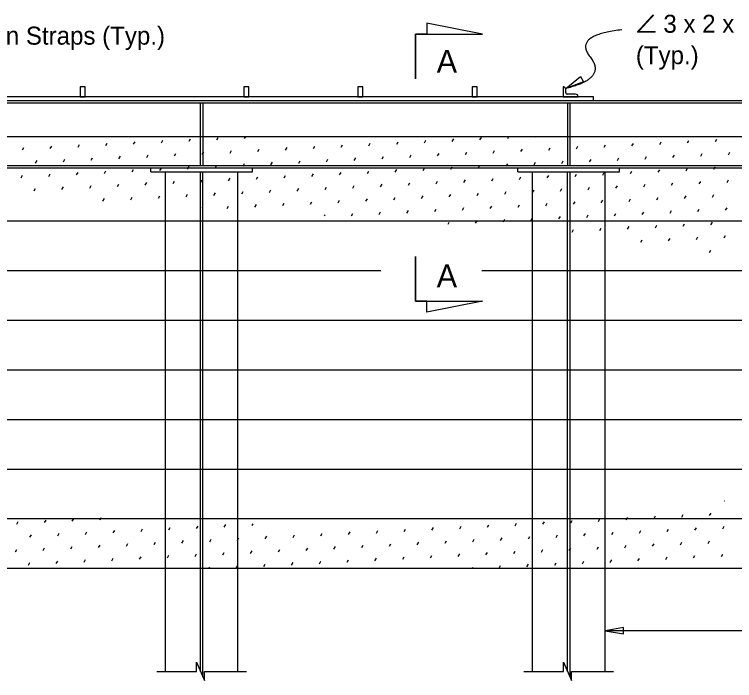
# Model space of a CAD drawing. Extents: x 10624 to 10731, y 76457 to 76509.
# Drawn here: x 10653.36 to 10665.46, y 76483.76 to 76494.95 of the extents above; entities that cross this region are included whole.
import ezdxf

# ---------------------------------------------------------------- set-up
doc = ezdxf.new("R2010")
doc.units = 0
for name, color, linetype in [('Dimension', 7, 'Continuous'), ('GroundLines', 7, 'Continuous'), ('SteelMisc', 7, 'Continuous'), ('SteelMisc_h', 7, 'Continuous'), ('Symbols', 7, 'Continuous'), ('TextStructures', 7, 'Continuous'), ('Wood', 7, 'Continuous'), ('Wood_h', 7, 'Continuous')]:
    doc.layers.add(name, color=color, linetype=linetype)

msp = doc.modelspace()

# ---------------------------------------------------------------- linework, layer by layer
at = {"layer": 'Dimension'}
for p, q in [((10655.365, 76492.769), (10655.389, 76492.811)), ((10655.831, 76492.793), (10655.855, 76492.835)), ((10656.298, 76492.818), (10656.322, 76492.86)), ((10656.764, 76492.842), (10656.788, 76492.884)), ((10657.23, 76492.866), (10657.248, 76492.897)), ((10657.697, 76492.891), (10657.701, 76492.897)), ((10659.784, 76492.767), (10659.808, 76492.809)), ((10660.25, 76492.792), (10660.274, 76492.834)), ((10660.717, 76492.816), (10660.741, 76492.858)), ((10661.183, 76492.84), (10661.207, 76492.882)), ((10661.649, 76492.865), (10661.668, 76492.897)), ((10662.116, 76492.889), (10662.121, 76492.897)), ((10664.203, 76492.765), (10664.227, 76492.807)), ((10664.669, 76492.79), (10664.693, 76492.832)), ((10665.136, 76492.814), (10665.16, 76492.856)), ((10653.499, 76492.672), (10653.523, 76492.714)), ((10653.965, 76492.696), (10653.99, 76492.738)), ((10654.432, 76492.72), (10654.456, 76492.762)), ((10654.898, 76492.745), (10654.922, 76492.787)), ((10657.451, 76492.645), (10657.476, 76492.687)), ((10657.918, 76492.67), (10657.942, 76492.712)), ((10658.384, 76492.694), (10658.409, 76492.736)), ((10658.851, 76492.718), (10658.875, 76492.76)), ((10659.317, 76492.743), (10659.341, 76492.785)), ((10661.87, 76492.644), (10661.895, 76492.686)), ((10662.337, 76492.668), (10662.361, 76492.71)), ((10662.803, 76492.692), (10662.828, 76492.734)), ((10663.27, 76492.717), (10663.294, 76492.759)), ((10663.736, 76492.741), (10663.76, 76492.783)), ((10655.119, 76492.524), (10655.144, 76492.566)), ((10655.586, 76492.548), (10655.61, 76492.59)), ((10656.052, 76492.572), (10656.076, 76492.614)), ((10656.519, 76492.597), (10656.543, 76492.639)), ((10656.985, 76492.621), (10657.009, 76492.663)), ((10659.538, 76492.522), (10659.563, 76492.564)), ((10660.005, 76492.546), (10660.029, 76492.588)), ((10660.471, 76492.571), (10660.495, 76492.613)), ((10660.938, 76492.595), (10660.962, 76492.637)), ((10661.404, 76492.619), (10661.428, 76492.661)), ((10664.424, 76492.544), (10664.448, 76492.586)), ((10664.89, 76492.569), (10664.914, 76492.611)), ((10665.357, 76492.593), (10665.381, 76492.635)), ((10653.72, 76492.451), (10653.744, 76492.493)), ((10654.186, 76492.475), (10654.211, 76492.517)), ((10654.653, 76492.499), (10654.677, 76492.541)), ((10657.206, 76492.4), (10657.23, 76492.442)), ((10657.672, 76492.424), (10657.697, 76492.466)), ((10658.139, 76492.449), (10658.163, 76492.491)), ((10658.605, 76492.473), (10658.63, 76492.515)), ((10659.072, 76492.497), (10659.096, 76492.539)), ((10662.091, 76492.423), (10662.116, 76492.465)), ((10662.558, 76492.447), (10662.582, 76492.489)), ((10663.024, 76492.471), (10663.049, 76492.513)), ((10663.491, 76492.496), (10663.515, 76492.538)), ((10663.957, 76492.52), (10663.982, 76492.562)), ((10655.34, 76492.303), (10655.365, 76492.345)), ((10655.807, 76492.327), (10655.831, 76492.369)), ((10656.273, 76492.351), (10656.297, 76492.393)), ((10656.74, 76492.376), (10656.764, 76492.418)), ((10659.759, 76492.301), (10659.784, 76492.343)), ((10660.226, 76492.325), (10660.25, 76492.367)), ((10660.692, 76492.349), (10660.716, 76492.391)), ((10661.159, 76492.374), (10661.183, 76492.416)), ((10661.625, 76492.398), (10661.649, 76492.44)), ((10664.178, 76492.299), (10664.203, 76492.341)), ((10664.645, 76492.323), (10664.669, 76492.365)), ((10665.111, 76492.348), (10665.135, 76492.39)), ((10653.475, 76492.205), (10653.499, 76492.247)), ((10653.941, 76492.229), (10653.965, 76492.271)), ((10654.407, 76492.254), (10654.432, 76492.296)), ((10654.874, 76492.278), (10654.898, 76492.32)), ((10657.427, 76492.179), (10657.451, 76492.221)), ((10657.894, 76492.203), (10657.918, 76492.245)), ((10658.36, 76492.228), (10658.384, 76492.27)), ((10658.826, 76492.252), (10658.851, 76492.294)), ((10659.293, 76492.276), (10659.317, 76492.318)), ((10661.846, 76492.177), (10661.87, 76492.219)), ((10662.313, 76492.202), (10662.337, 76492.244)), ((10662.779, 76492.226), (10662.803, 76492.268)), ((10663.245, 76492.25), (10663.27, 76492.292)), ((10663.712, 76492.275), (10663.736, 76492.317)), ((10655.095, 76492.057), (10655.119, 76492.099)), ((10655.561, 76492.082), (10655.586, 76492.124)), ((10656.028, 76492.106), (10656.052, 76492.148)), ((10656.494, 76492.13), (10656.518, 76492.172)), ((10656.961, 76492.155), (10656.985, 76492.197)), ((10659.514, 76492.055), (10659.538, 76492.097)), ((10659.98, 76492.08), (10660.005, 76492.122)), ((10660.447, 76492.104), (10660.471, 76492.146)), ((10660.913, 76492.128), (10660.937, 76492.17)), ((10661.38, 76492.153), (10661.404, 76492.195)), ((10663.933, 76492.054), (10663.957, 76492.096)), ((10664.399, 76492.078), (10664.424, 76492.12)), ((10664.866, 76492.102), (10664.89, 76492.144)), ((10665.332, 76492.127), (10665.356, 76492.169)), ((10653.696, 76491.984), (10653.72, 76492.026)), ((10654.162, 76492.008), (10654.186, 76492.05)), ((10654.628, 76492.033), (10654.653, 76492.075)), ((10657.182, 76491.934), (10657.206, 76491.976)), ((10657.648, 76491.958), (10657.672, 76492)), ((10658.115, 76491.982), (10658.139, 76492.024)), ((10658.581, 76492.007), (10658.605, 76492.049)), ((10659.047, 76492.031), (10659.072, 76492.073)), ((10661.601, 76491.932), (10661.625, 76491.974)), ((10662.067, 76491.956), (10662.091, 76491.998)), ((10662.534, 76491.98), (10662.558, 76492.022)), ((10663, 76492.005), (10663.024, 76492.047)), ((10663.466, 76492.029), (10663.491, 76492.071)), ((10654.849, 76491.812), (10654.874, 76491.854)), ((10655.316, 76491.836), (10655.34, 76491.878)), ((10655.782, 76491.86), (10655.807, 76491.902)), ((10656.249, 76491.885), (10656.273, 76491.927)), ((10656.715, 76491.909), (10656.74, 76491.951)), ((10659.268, 76491.81), (10659.293, 76491.852)), ((10659.735, 76491.834), (10659.759, 76491.876)), ((10660.201, 76491.859), (10660.226, 76491.901)), ((10660.668, 76491.883), (10660.692, 76491.925)), ((10661.134, 76491.907), (10661.159, 76491.949)), ((10663.687, 76491.808), (10663.712, 76491.85)), ((10664.154, 76491.833), (10664.178, 76491.874)), ((10664.62, 76491.857), (10664.645, 76491.899)), ((10665.087, 76491.881), (10665.111, 76491.923)), ((10656.936, 76491.688), (10656.961, 76491.73)), ((10657.403, 76491.713), (10657.427, 76491.755)), ((10657.869, 76491.737), (10657.893, 76491.779)), ((10658.336, 76491.761), (10658.36, 76491.803)), ((10658.802, 76491.786), (10658.826, 76491.828)), ((10661.355, 76491.686), (10661.38, 76491.728)), ((10661.822, 76491.711), (10661.846, 76491.753)), ((10662.288, 76491.735), (10662.312, 76491.777)), ((10662.755, 76491.759), (10662.779, 76491.801)), ((10663.221, 76491.784), (10663.245, 76491.826)), ((10656.492, 76491.702), (10656.494, 76491.706)), ((10659.023, 76491.565), (10659.047, 76491.607)), ((10659.49, 76491.589), (10659.514, 76491.631)), ((10659.956, 76491.613), (10659.98, 76491.655)), ((10660.422, 76491.638), (10660.447, 76491.68)), ((10660.889, 76491.662), (10660.913, 76491.704)), ((10663.442, 76491.563), (10663.466, 76491.605)), ((10663.909, 76491.587), (10663.933, 76491.629)), ((10664.375, 76491.611), (10664.399, 76491.653)), ((10664.841, 76491.636), (10664.866, 76491.678)), ((10665.308, 76491.66), (10665.332, 76491.702)), ((10658.571, 76491.564), (10658.581, 76491.582)), ((10661.11, 76491.441), (10661.134, 76491.483)), ((10661.576, 76491.465), (10661.601, 76491.507)), ((10662.043, 76491.49), (10662.067, 76491.532)), ((10662.509, 76491.514), (10662.533, 76491.556)), ((10662.976, 76491.538), (10663, 76491.58)), ((10660.649, 76491.427), (10660.668, 76491.459)), ((10663.197, 76491.317), (10663.221, 76491.359)), ((10663.663, 76491.342), (10663.687, 76491.384)), ((10664.13, 76491.366), (10664.154, 76491.408)), ((10664.596, 76491.39), (10664.62, 76491.432)), ((10665.062, 76491.415), (10665.087, 76491.457)), ((10662.73, 76491.293), (10662.755, 76491.335)), ((10665.283, 76491.194), (10665.308, 76491.236)), ((10663.884, 76491.121), (10663.908, 76491.163)), ((10664.351, 76491.145), (10664.375, 76491.187)), ((10664.817, 76491.169), (10664.841, 76491.211)), ((10665.038, 76490.948), (10665.062, 76490.99)), ((10665.285, 76486.775), (10665.288, 76486.78)), ((10664.107, 76486.481), (10664.131, 76486.523)), ((10664.573, 76486.505), (10664.598, 76486.547)), ((10665.04, 76486.529), (10665.064, 76486.571)), ((10653.403, 76486.387), (10653.428, 76486.429)), ((10653.87, 76486.411), (10653.894, 76486.453)), ((10654.336, 76486.436), (10654.36, 76486.478)), ((10654.803, 76486.46), (10654.823, 76486.496)), ((10661.775, 76486.359), (10661.799, 76486.401)), ((10662.241, 76486.383), (10662.266, 76486.425)), ((10662.708, 76486.408), (10662.732, 76486.45)), ((10663.174, 76486.432), (10663.198, 76486.474)), ((10663.641, 76486.456), (10663.665, 76486.498)), ((10655.024, 76486.239), (10655.048, 76486.281)), ((10655.49, 76486.263), (10655.514, 76486.305)), ((10655.956, 76486.288), (10655.981, 76486.33)), ((10656.423, 76486.312), (10656.447, 76486.354)), ((10656.889, 76486.336), (10656.914, 76486.378)), ((10657.356, 76486.361), (10657.373, 76486.391)), ((10659.443, 76486.237), (10659.467, 76486.279)), ((10659.909, 76486.261), (10659.933, 76486.303)), ((10660.375, 76486.286), (10660.4, 76486.328)), ((10660.842, 76486.31), (10660.866, 76486.352)), ((10661.308, 76486.334), (10661.333, 76486.376)), ((10663.862, 76486.235), (10663.886, 76486.277)), ((10664.328, 76486.26), (10664.352, 76486.302)), ((10664.794, 76486.284), (10664.819, 76486.326)), ((10665.261, 76486.308), (10665.285, 76486.35)), ((10653.624, 76486.166), (10653.649, 76486.208)), ((10654.091, 76486.19), (10654.115, 76486.232)), ((10654.557, 76486.214), (10654.581, 76486.256)), ((10657.11, 76486.115), (10657.135, 76486.157)), ((10657.577, 76486.14), (10657.601, 76486.182)), ((10658.043, 76486.164), (10658.068, 76486.206)), ((10658.51, 76486.188), (10658.534, 76486.23)), ((10658.976, 76486.213), (10659, 76486.255)), ((10661.529, 76486.113), (10661.554, 76486.155)), ((10661.996, 76486.138), (10662.02, 76486.18)), ((10662.462, 76486.162), (10662.487, 76486.204)), ((10662.929, 76486.187), (10662.953, 76486.229)), ((10663.395, 76486.211), (10663.419, 76486.253)), ((10654.778, 76485.993), (10654.803, 76486.035)), ((10655.245, 76486.018), (10655.269, 76486.06)), ((10655.711, 76486.042), (10655.735, 76486.084)), ((10656.178, 76486.067), (10656.202, 76486.109)), ((10656.644, 76486.091), (10656.668, 76486.133)), ((10659.197, 76485.992), (10659.222, 76486.034)), ((10659.664, 76486.016), (10659.688, 76486.058)), ((10660.13, 76486.04), (10660.154, 76486.082)), ((10660.597, 76486.065), (10660.621, 76486.107)), ((10661.063, 76486.089), (10661.087, 76486.131)), ((10663.616, 76485.99), (10663.641, 76486.032)), ((10664.083, 76486.014), (10664.107, 76486.056)), ((10664.549, 76486.039), (10664.573, 76486.081)), ((10665.016, 76486.063), (10665.04, 76486.105)), ((10653.379, 76485.92), (10653.403, 76485.962)), ((10653.845, 76485.945), (10653.87, 76485.987)), ((10654.312, 76485.969), (10654.336, 76486.011)), ((10656.865, 76485.87), (10656.889, 76485.912)), ((10657.331, 76485.894), (10657.356, 76485.936)), ((10657.798, 76485.919), (10657.822, 76485.961)), ((10658.264, 76485.943), (10658.289, 76485.985)), ((10658.731, 76485.967), (10658.755, 76486.009)), ((10661.284, 76485.868), (10661.308, 76485.91)), ((10661.75, 76485.892), (10661.775, 76485.934)), ((10662.217, 76485.917), (10662.241, 76485.959)), ((10662.683, 76485.941), (10662.708, 76485.983)), ((10663.15, 76485.965), (10663.174, 76486.007)), ((10654.533, 76485.748), (10654.557, 76485.79)), ((10654.999, 76485.772), (10655.024, 76485.814)), ((10655.466, 76485.797), (10655.49, 76485.839)), ((10655.932, 76485.821), (10655.956, 76485.863)), ((10656.399, 76485.845), (10656.423, 76485.887)), ((10659.418, 76485.771), (10659.443, 76485.813)), ((10659.885, 76485.795), (10659.909, 76485.837)), ((10660.351, 76485.819), (10660.375, 76485.861)), ((10660.818, 76485.844), (10660.842, 76485.886)), ((10663.837, 76485.769), (10663.862, 76485.811)), ((10664.304, 76485.793), (10664.328, 76485.835)), ((10664.77, 76485.818), (10664.794, 76485.859)), ((10665.237, 76485.842), (10665.261, 76485.884)), ((10653.6, 76485.699), (10653.624, 76485.741)), ((10654.066, 76485.724), (10654.091, 76485.766)), ((10657.086, 76485.649), (10657.11, 76485.691)), ((10657.552, 76485.673), (10657.577, 76485.715)), ((10658.019, 76485.698), (10658.043, 76485.74)), ((10658.485, 76485.722), (10658.51, 76485.764)), ((10658.952, 76485.746), (10658.976, 76485.788)), ((10661.505, 76485.647), (10661.529, 76485.689)), ((10661.971, 76485.671), (10661.996, 76485.713)), ((10662.438, 76485.696), (10662.462, 76485.738)), ((10662.904, 76485.72), (10662.929, 76485.762)), ((10663.371, 76485.744), (10663.395, 76485.786)), ((10656.177, 76485.641), (10656.177, 76485.642)), ((10656.629, 76485.641), (10656.644, 76485.666)), ((10661.049, 76485.641), (10661.063, 76485.665)), ((10670.147, 76484.596), (10663.283, 76484.596))]:
    msp.add_line(p, q, dxfattribs=at)
for points in [[(10662.624, 76493.705), (10662.869, 76493.906), (10662.921, 76493.815)], [(10663.283, 76484.596), (10663.595, 76484.543), (10663.595, 76484.649)]]:
    msp.add_lwpolyline(points, close=True, dxfattribs=at)
msp.add_open_spline([(10663.566, 76494.691), (10662.74, 76494.598), (10663.324, 76493.874), (10662.624, 76493.705)], degree=2, dxfattribs=at)
at = {"layer": 'GroundLines'}
msp.add_line((10629.323, 76487.307), (10670.364, 76487.307), dxfattribs=at)
at = {"layer": 'SteelMisc'}
for p, q in [((10662.581, 76493.733), (10662.581, 76493.567)), ((10662.623, 76493.634), (10662.623, 76493.692)), ((10662.581, 76493.567), (10662.831, 76493.567)), ((10662.79, 76493.608), (10662.649, 76493.608)), ((10631.234, 76493.504), (10669.45, 76493.504)), ((10631.234, 76493.462), (10669.45, 76493.462)), ((10656.491, 76492.406), (10656.491, 76493.462)), ((10656.532, 76492.406), (10656.532, 76493.462)), ((10662.657, 76492.406), (10662.657, 76493.462)), ((10662.699, 76492.406), (10662.699, 76493.462)), ((10630.987, 76492.37), (10669.696, 76492.37)), ((10631.234, 76492.412), (10669.45, 76492.412)), ((10655.654, 76492.307), (10655.654, 76492.37)), ((10657.363, 76492.307), (10657.363, 76492.37)), ((10661.821, 76492.307), (10661.821, 76492.37)), ((10663.529, 76492.307), (10663.529, 76492.37)), ((10655.654, 76492.307), (10657.363, 76492.307)), ((10655.901, 76487.307), (10655.901, 76492.307)), ((10657.116, 76487.307), (10657.116, 76492.307)), ((10661.821, 76492.307), (10663.529, 76492.307)), ((10662.067, 76487.307), (10662.067, 76492.307)), ((10663.283, 76487.307), (10663.283, 76492.307))]:
    msp.add_line(p, q, dxfattribs=at)
for points in [[(10654.467, 76493.567), (10654.55, 76493.567), (10654.55, 76493.733), (10654.467, 76493.733)], [(10657.217, 76493.567), (10657.3, 76493.567), (10657.3, 76493.733), (10657.217, 76493.733)], [(10659.133, 76493.567), (10659.217, 76493.567), (10659.217, 76493.733), (10659.133, 76493.733)], [(10661.05, 76493.567), (10661.133, 76493.567), (10661.133, 76493.733), (10661.05, 76493.733)], [(10637.592, 76493.504), (10663.092, 76493.504), (10663.092, 76493.567), (10637.592, 76493.567)]]:
    msp.add_lwpolyline(points, close=True, dxfattribs=at)
for centre, radius, start, end in [((10662.581, 76493.692), 0.0417, 0, 90), ((10662.649, 76493.634), 0.026, 180, 270), ((10662.79, 76493.567), 0.0417, 0, 90)]:
    msp.add_arc(centre, radius, start, end, dxfattribs=at)
at = {"layer": 'SteelMisc_h'}
for p, q in [((10656.487, 76483.913), (10656.487, 76492.307)), ((10656.529, 76483.816), (10656.529, 76492.307)), ((10662.654, 76483.913), (10662.654, 76492.307)), ((10662.696, 76483.816), (10662.696, 76492.307)), ((10655.901, 76483.913), (10655.901, 76487.307)), ((10657.116, 76483.913), (10657.116, 76487.307)), ((10662.067, 76483.913), (10662.067, 76487.307)), ((10663.283, 76483.913), (10663.283, 76487.307))]:
    msp.add_line(p, q, dxfattribs=at)
at = {"layer": 'Symbols'}
for points in [[(10660.101, 76493.865), (10660.101, 76494.615), (10661.226, 76494.615), (10660.289, 76494.802), (10660.289, 76494.615), (10660.101, 76494.615)], [(10660.101, 76490.884), (10660.101, 76490.134), (10661.226, 76490.134), (10660.289, 76489.946), (10660.289, 76490.134), (10660.101, 76490.134)]]:
    msp.add_lwpolyline(points, close=True, dxfattribs=at)
for points in [[(10655.755, 76483.913), (10656.42, 76483.913), (10656.42, 76484.068), (10656.555, 76483.758), (10656.555, 76483.913), (10657.261, 76483.913)], [(10661.921, 76483.913), (10662.587, 76483.913), (10662.587, 76484.068), (10662.722, 76483.758), (10662.722, 76483.913), (10663.428, 76483.913)]]:
    msp.add_lwpolyline(points, dxfattribs=at)
at = {"layer": 'TextStructures'}
msp.add_line((10631.234, 76492.897), (10669.486, 76492.897), dxfattribs=at)
at = {"layer": 'Wood'}
for p, q in [((10655.901, 76491.474), (10650.949, 76491.474)), ((10662.067, 76491.474), (10657.116, 76491.474)), ((10668.234, 76491.474), (10663.283, 76491.474)), ((10655.901, 76490.641), (10650.949, 76490.641)), ((10659.52, 76490.641), (10657.116, 76490.641)), ((10662.067, 76490.641), (10661.216, 76490.641)), ((10668.234, 76490.641), (10663.283, 76490.641)), ((10655.901, 76489.807), (10650.949, 76489.807)), ((10662.067, 76489.807), (10657.116, 76489.807)), ((10668.234, 76489.807), (10663.283, 76489.807)), ((10655.901, 76488.974), (10650.949, 76488.974)), ((10662.067, 76488.974), (10657.116, 76488.974)), ((10668.234, 76488.974), (10663.283, 76488.974)), ((10655.901, 76488.141), (10650.949, 76488.141)), ((10662.067, 76488.141), (10657.116, 76488.141)), ((10668.234, 76488.141), (10663.283, 76488.141))]:
    msp.add_line(p, q, dxfattribs=at)
at = {"layer": 'Wood_h'}
for p, q in [((10657.116, 76491.474), (10655.901, 76491.474)), ((10663.283, 76491.474), (10662.067, 76491.474)), ((10657.116, 76490.641), (10655.901, 76490.641)), ((10663.283, 76490.641), (10662.067, 76490.641)), ((10657.116, 76489.807), (10655.901, 76489.807)), ((10663.283, 76489.807), (10662.067, 76489.807)), ((10657.116, 76488.974), (10655.901, 76488.974)), ((10663.283, 76488.974), (10662.067, 76488.974)), ((10657.116, 76488.141), (10655.901, 76488.141)), ((10663.283, 76488.141), (10662.067, 76488.141)), ((10669.45, 76486.474), (10631.234, 76486.474)), ((10669.45, 76485.641), (10631.234, 76485.641))]:
    msp.add_line(p, q, dxfattribs=at)

# ---------------------------------------------------------------- texts
at = {"layer": 'Dimension'}
msp.add_text('Deck Hold Down Straps (Typ.)', height=0.3024, dxfattribs=at).set_placement((10650.432, 76494.441))
at = {"layer": 'TextStructures'}
for s, height, p in [('∠ 3 x 2 x ', 0.3024, (10663.801, 76494.641)), ('(Typ.)', 0.3024, (10663.801, 76494.113)), ('A', 0.384, (10660.456, 76493.97)), ('A', 0.384, (10660.456, 76490.365))]:
    msp.add_text(s, height=height, dxfattribs=at).set_placement(p)

doc.saveas('drawing.dxf')
